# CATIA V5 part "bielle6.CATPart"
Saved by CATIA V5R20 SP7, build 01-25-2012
Part number: bielle6
Publications: "droite_bielle_6", "droite_pivot_6_5_7", "droite_pivot_6_1_2"
Bounding box of the stored display mesh (mm): x 0 to 0.5, y 2.07 to 2.08, z 1.17 to 2.17
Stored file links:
  U:\IAO\bielle6.CATPart
  U:\IAO\skl_brevet_iao.CATProduct
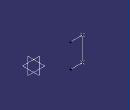
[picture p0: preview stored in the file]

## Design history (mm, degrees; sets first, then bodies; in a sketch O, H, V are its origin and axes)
Set1
  Point1 "point G": linked copy from another document
  Point2 "point B": linked copy from another document
Set2
  Line1 "droite_bielle_6": type PtPt, FirstPoint Point1, SecondPoint Point2
  Line2 "droite_pivot_6_5_7": type Normal, RefPoint Point1, RefSkin yz-plane, Start 0, End 0.5
  Line3 "droite_pivot_6_1_2": type Normal, RefPoint Point2, RefSkin yz-plane, Start 0, End 0.5
Body1 (main body)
